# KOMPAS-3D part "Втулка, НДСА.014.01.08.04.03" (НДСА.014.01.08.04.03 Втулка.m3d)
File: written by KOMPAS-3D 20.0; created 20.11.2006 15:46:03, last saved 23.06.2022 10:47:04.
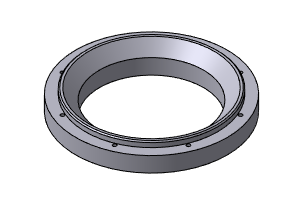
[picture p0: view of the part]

Document properties: Автор: Устинов А.В.; Организация: ЭСТО-Вакуум; Полное имя файла: C:\Users\cherbakova\Desktop\PLM\НДСА.014.01.08.04.03 Втулка.m3d

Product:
- Part/product: Втулка  | designation НДСА.014.01.08.04.03
    Материал: Сталь 20 ГОСТ 1050-88 (density 7859 kg/m3)
    Масса: 0.959708
    additional columns: <item xmlns="http://appius.ru/pdm" xmlns:xs="http://www.w3.org/2001/XMLSchema" x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; <item xmlns="http://appius.ru/pdm" xmlns:xs="http://www.w3.org/2001/XMLSchema" x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; <item xmlns="http://appius.ru/pdm" xmlns:xs="http://www.w3.org/2001/XMLSchema" x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; <item xmlns="http://appius.ru/pdm" xmlns:xs="http://www.w3.org/2001/XMLSchema" x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; <item xmlns="http://appius.ru/pdm" xmlns:xs="http://www.w3.org/2001/XMLSchema" x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; <item xmlns="http://appius.ru/pdm" xmlns:xs="http://www.w3.org/2001/XMLSchema" x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
    source file: НДСА.014.01.08.04.03 Втулка.CDW

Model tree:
1. Плоскость XY
2. Плоскость ZX
3. Плоскость ZY
4. Начало координат
5. Эскиз:1
6. Операция вращения:1
     Угол 1 = 360
7. Эскиз:2  (labels: Операция вращения:1)
8. Вырезать элемент выдавливания:1
     Расстояние 2 = 19
9. Условное изображение резьбы:1  (labels: Вырезать элемент выдавливания:1; Вырезать элемент выдавливания:1)
     Длина резьбы = 14; Шаг резьбы = 0.7; Номинальный диаметр резьбы = 4
10. Условное изображение резьбы:2  (labels: Вырезать элемент выдавливания:1; Вырезать элемент выдавливания:1)
     Длина резьбы = 14; Шаг резьбы = 0.7; Номинальный диаметр резьбы = 4
11. Условное изображение резьбы:3  (labels: Вырезать элемент выдавливания:1; Вырезать элемент выдавливания:1)
     Длина резьбы = 14; Шаг резьбы = 0.7; Номинальный диаметр резьбы = 4
12. Условное изображение резьбы:4  (labels: Вырезать элемент выдавливания:1; Вырезать элемент выдавливания:1)
     Длина резьбы = 14; Шаг резьбы = 0.7; Номинальный диаметр резьбы = 4
13. Условное изображение резьбы:5  (labels: Вырезать элемент выдавливания:1; Вырезать элемент выдавливания:1)
     Длина резьбы = 14; Шаг резьбы = 0.7; Номинальный диаметр резьбы = 4
14. Условное изображение резьбы:6  (labels: Вырезать элемент выдавливания:1; Вырезать элемент выдавливания:1)
     Длина резьбы = 14; Шаг резьбы = 0.7; Номинальный диаметр резьбы = 4
15. Условное изображение резьбы:7  (labels: Вырезать элемент выдавливания:1; Вырезать элемент выдавливания:1)
     Длина резьбы = 14; Шаг резьбы = 0.7; Номинальный диаметр резьбы = 4
16. Условное изображение резьбы:8  (labels: Вырезать элемент выдавливания:1; Вырезать элемент выдавливания:1)
     Длина резьбы = 14; Шаг резьбы = 0.7; Номинальный диаметр резьбы = 4
17. Ось пересечения двух плоскостей:1
18. Плоскость под углом:1  (labels: Сталь 20 ГОСТ 1050-88)
     Угол = 22.5

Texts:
  НДСА.014.01.08.04.03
